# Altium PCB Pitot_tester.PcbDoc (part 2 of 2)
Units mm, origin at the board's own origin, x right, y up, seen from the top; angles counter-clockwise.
Board outline 94.03 x 112.06 mm, 2 copper layers (Top Layer, Bottom Layer), stack 1.658 mm thick; 71 components, 60 nets, 466 pads, 349 vias.
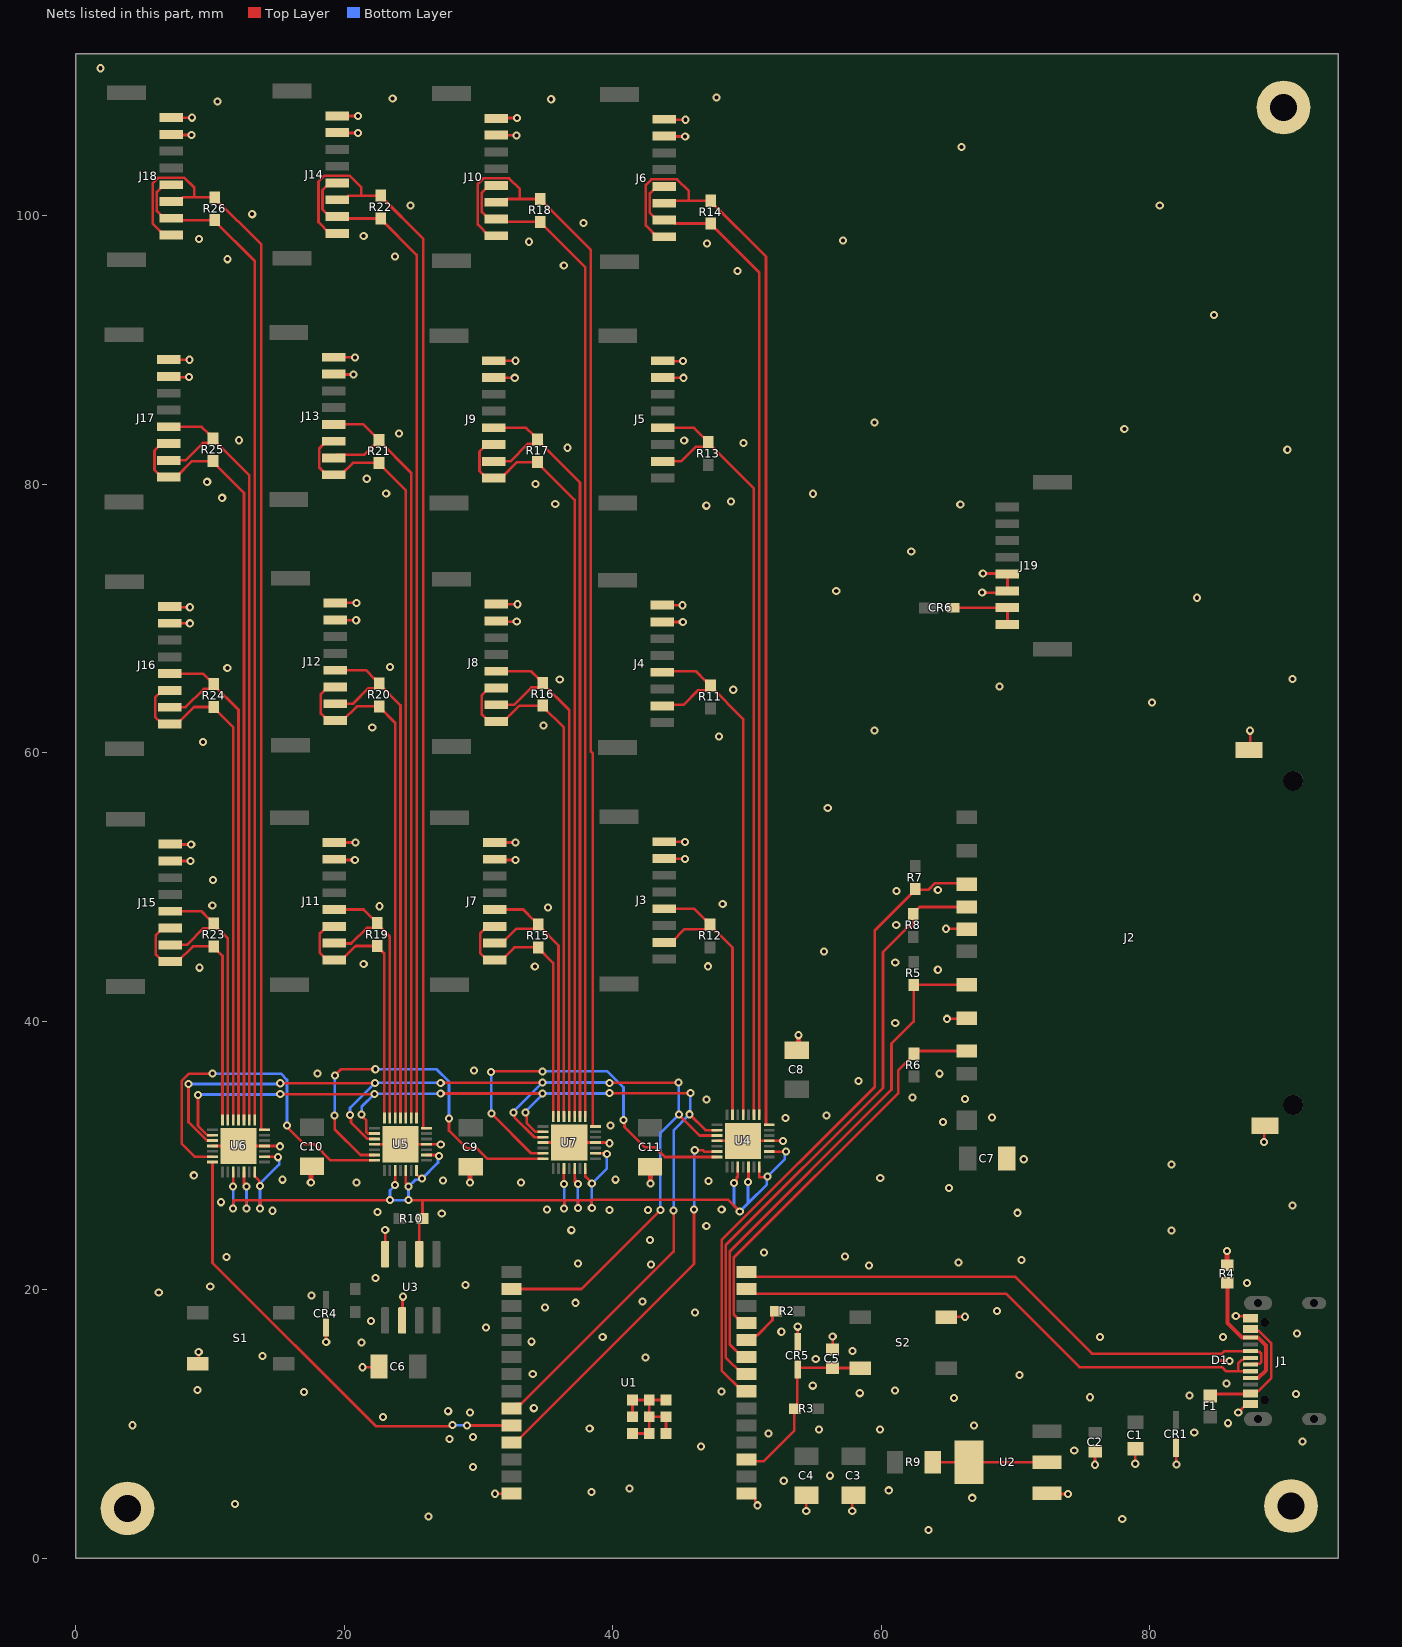
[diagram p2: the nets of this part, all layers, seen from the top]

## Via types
v1: diameter 0.61, hole 0.305, Top Layer to Bottom Layer, tented both sides, 187 vias
v2: diameter 0.6, hole 0.3, Top Layer to Bottom Layer, tented both sides, 162 vias

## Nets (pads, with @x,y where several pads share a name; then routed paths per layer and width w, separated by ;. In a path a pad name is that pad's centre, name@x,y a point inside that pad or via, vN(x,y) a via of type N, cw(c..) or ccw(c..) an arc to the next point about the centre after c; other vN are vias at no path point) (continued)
CANH_4: J6.1 J6.3 R14.2 U4.14 | length 83.5
  Top Layer w0.2: J6.1@43.836,98.444 43.29,98.444 42.459,99.274 42.459,102.307 42.877,102.724 44.795,102.724 45.658,101.861 45.658,101.129 ; J6.3@43.836,100.944 44.021,101.129 45.658,101.129 ; U4.14@51.651,32.29 51.411,32.29 51.41,32.291 51.41,96.964 47.295,101.079 R14.2@47.295,101.129 45.658,101.129
CANH_5: J7.1 J7.3 R15.2 U7.21 | length 20.7
  Top Layer w0.2: J7.3@31.187,47.071 30.64,47.071 30.11,46.541 30.11,45.101 30.64,44.571 J7.1@31.187,44.571 31.733,44.571 32.667,45.505 R15.2@34.442,45.505 34.442,45.455 35.554,44.344 U7.21@35.554,32.906
CANH_6: J8.1 J8.3 R16.2 U7.19 | length 39.2
  Top Layer w0.2: J8.3@31.318,64.825 30.772,64.825 30.242,64.294 30.242,62.855 30.772,62.325 J8.1@31.318,62.325 31.864,62.325 33.053,63.514 R16.2@34.773,63.514 34.773,63.464 36.354,61.882 U7.19@36.354,32.906
CANH_7: J9.1 J9.3 R17.2 U7.17 | length 57.7
  Top Layer w0.2: J9.3@31.14,82.96 30.594,82.96 30.064,82.43 30.064,80.99 30.594,80.46 J9.1@31.14,80.46 31.686,80.46 32.875,81.649 R17.2@34.392,81.649 34.392,81.599 37.154,78.837 U7.17@37.154,32.906
CANH_8: J10.1 J10.3 R18.2 U7.14 | length 84
  Top Layer w0.2: J10.3@30.772,101.014 J10.3@31.318,101.014 31.864,101.014 32.106,101.256 33.071,101.256 ; J10.1@31.318,98.514 30.772,98.514 29.942,99.344 29.942,102.377 30.359,102.794 32.277,102.794 33.071,102.001 33.071,101.256 ; U7.14@38.697,32.163 38.508,32.163 38.506,32.164 38.506,59.949 38.36,60.095 38.36,97.441 34.595,101.206 R18.2@34.595,101.256 33.071,101.256
CANH_9: J11.1 J11.3 R19.2 U5.21 | length 20.7
  Top Layer w0.2: J11.3@19.249,47.071 18.702,47.071 18.172,46.541 18.172,45.101 18.702,44.571 J11.1@19.249,44.571 19.795,44.571 20.83,45.607 R19.2@22.454,45.607 22.454,45.557 22.981,45.029 U5.21@22.981,32.779 U5.21@22.982,32.78
CANH_10: J12.1 J12.3 R20.2 U5.19 | length 38.9
  Top Layer w0.2: J12.3@19.325,64.902 18.779,64.902 18.248,64.371 18.248,62.932 18.779,62.402 J12.1@19.325,62.402 19.871,62.402 20.932,63.463 R20.2@22.606,63.463 22.606,63.413 23.781,62.238 U5.19@23.781,32.779
CANH_11: J13.1 J13.3 R21.2 U5.17 | length 57.4
  Top Layer w0.2: J13.3@19.202,83.214 18.656,83.214 18.126,82.684 18.126,81.244 18.656,80.714 J13.1@19.202,80.714 19.749,80.714 20.633,81.598 R21.2@22.581,81.598 22.581,81.548 24.581,79.548 U5.17@24.581,32.779
CANH_12: J14.1 J14.3 R22.2 U5.14 | length 83.5
  Top Layer w0.2: J14.1@19.452,98.698 18.906,98.698 18.075,99.528 18.075,102.561 18.493,102.978 20.411,102.978 21.26,102.129 21.26,101.51 ; J14.3@19.452,101.198 19.998,101.198 20.31,101.51 21.26,101.51 ; U5.14@26.124,32.036 25.884,32.036 25.883,32.037 25.883,98.285 22.708,101.46 R22.2@22.708,101.51 21.26,101.51
CANH_13: J15.1 J15.3 R23.2 U6.21 | length 20.9
  Top Layer w0.2: J15.3@7.031,46.944 6.485,46.944 5.955,46.414 5.955,44.974 6.485,44.444 J15.1@7.031,44.444 7.577,44.444 8.715,45.581 R23.2@10.262,45.581 10.262,45.531 10.916,44.877 U6.21@10.916,32.652
CANH_14: J16.1 J16.3 R24.2 U6.19 | length 39.2
  Top Layer w0.2: J16.3@6.98,64.648 6.434,64.648 5.904,64.117 5.904,62.678 6.434,62.148 J16.1@6.98,62.148 7.526,62.148 8.791,63.412 R24.2@10.262,63.412 10.262,63.362 11.716,61.908 U6.19@11.716,32.652 U6.19@11.717,32.653
CANH_15: J17.1 J17.3 R25.2 U6.17 | length 57.8
  Top Layer w0.2: J17.3@6.93,83.037 6.383,83.037 5.853,82.507 5.853,81.067 6.383,80.537 J17.1@6.93,80.537 7.476,80.537 8.664,81.725 R25.2@10.211,81.725 10.211,81.675 12.516,79.37 U6.17@12.516,32.652 U6.17@12.517,32.653
CANH_16: J18.1 J18.3 R26.2 U6.14 | length 83.6
  Top Layer w0.2: J18.1@7.107,98.571 6.561,98.571 5.731,99.401 5.731,102.434 6.148,102.851 8.066,102.851 8.814,102.104 8.814,101.383 ; J18.3@7.107,101.071 7.653,101.071 7.965,101.383 8.814,101.383 ; U6.14@14.059,31.909 13.819,31.909 13.818,31.91 13.818,97.853 10.338,101.333 R26.2@10.338,101.383 8.814,101.383
CANL: R10.1 U3.6 U4.3 U4.5 U4.7 U4.9 U5.3 U5.5 U5.7 U5.9 U6.3 U6.5 U6.7 U6.9 U7.3 U7.5 U7.7 U7.9 | length 94.7
  Top Layer w0.2: v2(11.709,26.06) 11.709,26.645 11.735,26.67 12.725,26.67 ; v2(11.709,27.686) 11.716,27.692 U6.3@11.716,28.765 ; v2@12.516,27.803 U6.5@12.516,28.765 ; v2(12.7,26.035) 12.7,26.645 12.725,26.67 ; U6.7@13.316,28.765 13.316,28.461 13.665,28.111 13.665,27.762 v2(13.716,27.711) ; v2(13.716,26.06) 13.716,26.645 13.741,26.67 ; U6.9@14.059,29.909 14.061,29.907 15.026,29.907 v2(15.062,29.87) ; v2(23.393,26.67) 13.741,26.67 ; v2(23.774,27.788) 23.781,27.794 U5.3@23.781,28.892 ; U5.5@24.581,28.892 24.581,27.93 24.79,27.721 v2(24.79,27.678) ; v2(24.774,26.67) 25.806,26.67 ; U5.7@25.381,28.892 25.381,28.588 25.698,28.27 v2(25.781,28.27) ; U3.6@25.578,22.993 25.578,25.058 R10.1@25.818,25.298 25.818,26.658 25.806,26.67 ; U5.9@26.124,30.036 26.126,30.034 26.989,30.034 v2(27.051,29.972) ; U7.3@36.354,29.019 36.354,27.883 v2(36.373,27.864) ; v2(36.373,26.035) 36.373,26.645 36.398,26.67 ; U7.5@37.154,29.019 37.154,28.313 37.186,28.281 v2@37.186,27.981 ; v2(37.414,26.086) 37.414,26.645 37.44,26.67 ; U7.7@37.954,29.019 37.954,28.43 38.329,28.055 38.329,28.016 v2(38.43,27.915) ; v2(38.43,26.086) 38.43,26.645 38.456,26.67 ; U7.9@38.697,30.163 38.699,30.161 39.486,30.161 v2(39.548,30.099) ; v2@49.225,28.083 49.225,28.357 49.308,28.44 U4.3@49.308,29.146 ; v2(49.454,25.832) 48.573,26.713 38.498,26.713 38.456,26.67 ; v2(50.063,28.016) 50.108,28.061 U4.5@50.108,29.146 ; U4.7@50.908,29.146 50.908,28.387 51.476,28.387 v2(51.537,28.448) ; U4.9@51.651,30.29 v2(52.889,30.29) ; 12.725,26.67 13.741,26.67 ; 25.806,26.67 36.398,26.67 ; 36.398,26.67 37.44,26.67 ; 37.44,26.67 38.456,26.67
  Bottom Layer w0.2: v2(11.709,26.06) v2(11.709,27.686) ; v2(12.7,26.035) 12.708,26.043 12.708,27.678 v2(12.716,27.686) ; v2(13.716,26.06) v2(13.716,27.711) 13.793,27.788 13.793,27.988 15.139,29.334 15.139,29.794 v2(15.062,29.87) ; v2(23.774,27.788) 23.393,27.407 v2(23.393,26.67) v2(24.774,26.67) 24.782,26.678 24.782,27.67 v2(24.79,27.678) 25.306,28.194 25.704,28.194 26.974,29.464 26.974,29.895 v2(27.051,29.972) ; v2(36.373,26.035) v2(36.373,27.864) ; v2(37.389,27.864) 37.389,26.111 v2(37.414,26.086) ; v2(38.43,26.086) v2(38.43,27.915) 39.548,29.032 v2(39.548,30.099) ; v2(49.022,27.965) 49.022,26.264 v2(49.454,25.832) 50.063,26.441 ; v2(50.063,28.016) 50.063,26.441 ; v2(52.889,30.29) 52.812,30.213 52.812,29.724 v2(51.537,28.448) 51.47,28.381 51.47,27.848 50.063,26.441
CANL_1: J3.2 J3.4 R12.1 U4.20 | length 22.8
  Top Layer w0.2: J3.2@43.815,45.878 44.361,45.878 45.346,46.863 46.944,46.863 47.244,47.163 R12.1@47.244,47.205 47.244,47.255 46.944,47.555 46.894,47.555 46.071,48.378 J3.4@43.815,48.378 ; R12.1@47.244,47.155 48.908,45.491 U4.20@48.908,33.033
CANL_2: J4.2 J4.4 R11.1 U4.18 | length 40.7
  Top Layer w0.2: J4.2@43.891,63.575 45.263,63.575 46.349,64.66 46.969,64.66 47.269,64.96 49.708,62.522 U4.18@49.708,33.033 ; J4.4@43.891,66.075 46.205,66.075 46.919,65.36 46.969,65.36 47.269,65.06 R11.1@47.269,65.01
CANL_3: J5.2 J5.4 R13.1 U4.16 | length 59.3
  Top Layer w0.2: J5.2@43.713,81.71 45.085,81.71 46.171,82.796 46.817,82.796 47.117,83.096 50.508,79.705 U4.16@50.508,33.033 ; J5.4@43.713,84.21 46.053,84.21 46.767,83.496 46.817,83.496 47.117,83.196 R13.1@47.117,83.146
CANL_4: J6.2 J6.4 R14.1 U4.15 | length 75.5
  Top Layer w0.2: J6.4@43.836,102.194 43.29,102.194 42.759,101.664 42.759,100.224 43.29,99.694 J6.2@43.836,99.694 44.382,99.694 44.647,99.429 R14.1@47.295,99.429 47.295,99.379 50.908,95.766 U4.15@50.908,33.033
CANL_5: J7.2 J7.4 R15.1 U7.20 | length 22.5
  Top Layer w0.2: J7.2@31.187,45.821 31.733,45.821 32.8,46.888 34.142,46.888 34.442,47.188 R15.1@34.442,47.205 34.442,47.255 34.142,47.555 34.092,47.555 33.327,48.321 J7.4@31.187,48.321 ; R15.1@34.442,47.155 35.954,45.644 U7.20@35.954,32.906
CANL_6: J8.2 J8.4 R16.1 U7.18 | length 41
  Top Layer w0.2: J8.2@31.318,63.575 32.639,63.575 33.928,64.864 34.473,64.864 34.773,65.164 36.754,63.182 U7.18@36.754,32.906 ; J8.4@31.318,66.075 33.912,66.075 34.423,65.564 34.473,65.564 34.773,65.264 R16.1@34.773,65.214
CANL_7: J9.2 J9.4 R17.1 U7.16 | length 59.2
  Top Layer w0.2: J9.2@31.14,81.71 32.36,81.71 33.649,82.999 34.092,82.999 34.392,83.299 37.554,80.137 U7.16@37.554,32.906 ; J9.4@31.14,84.21 33.531,84.21 34.042,83.699 34.092,83.699 34.392,83.399 R17.1@34.392,83.349
CANL_8: J10.2 J10.4 R18.1 U7.15 | length 75.4
  Top Layer w0.2: J10.4@31.318,102.264 30.772,102.264 30.242,101.734 30.242,100.294 30.772,99.764 J10.2@31.318,99.764 31.526,99.556 R18.1@34.595,99.556 34.595,99.506 37.954,96.147 U7.15@37.954,32.906
CANL_9: J11.2 J11.4 R19.1 U5.20 | length 22.4
  Top Layer w0.2: J11.2@19.249,45.821 19.277,45.793 20.507,45.793 21.671,46.957 22.154,46.957 R19.1@22.454,47.257 ; J11.4@19.249,48.321 21.439,48.321 22.104,47.657 22.154,47.657 22.454,47.357 R19.1@22.454,47.307 R19.1@22.454,47.257 ; U5.20@23.381,32.779 23.381,46.329 R19.1@22.454,47.257
CANL_10: J12.2 J12.4 R20.1 U5.18 | length 40.6
  Top Layer w0.2: J12.2@19.325,63.652 20.623,63.652 21.784,64.813 22.306,64.813 22.606,65.113 24.181,63.538 U5.18@24.181,32.779 ; J12.4@19.325,66.152 21.617,66.152 22.256,65.513 22.306,65.513 22.606,65.213 R20.1@22.606,65.163
CANL_11: J13.2 J13.4 R21.1 U5.16 | length 59.3
  Top Layer w0.2: J13.2@19.202,81.964 19.433,82.194 21.477,82.194 22.231,82.948 22.281,82.948 22.581,83.248 24.981,80.848 U5.16@24.981,32.779 ; J13.4@19.202,84.464 21.415,84.464 22.231,83.648 22.281,83.648 22.581,83.348 R21.1@22.581,83.298
CANL_12: J14.2 J14.4 R22.1 U5.15 | length 75.5
  Top Layer w0.2: J14.4@19.452,102.448 18.906,102.448 18.375,101.918 18.375,100.478 18.906,99.948 J14.2@19.452,99.948 19.59,99.81 R22.1@22.708,99.81 22.708,99.76 25.381,97.087 U5.15@25.381,32.779
CANL_13: J15.2 J15.4 R23.1 U6.20 | length 22.6
  Top Layer w0.2: J15.2@7.031,45.694 8.266,45.694 9.503,46.931 9.962,46.931 R23.1@10.262,47.231 ; J15.4@7.031,48.194 9.349,48.194 9.912,47.631 9.962,47.631 10.262,47.331 R23.1@10.262,47.281 R23.1@10.262,47.231 ; U6.20@11.316,32.652 11.316,46.177 R23.1@10.262,47.231
CANL_14: J16.2 J16.4 R24.1 U6.18 | length 40.8
  Top Layer w0.2: J16.2@6.98,63.398 8.177,63.398 9.541,64.762 9.962,64.762 10.262,65.062 12.116,63.208 U6.18@12.116,32.652 U6.18@12.117,32.653 ; J16.4@6.98,65.898 9.476,65.898 9.912,65.462 9.962,65.462 10.262,65.162 R24.1@10.262,65.112
CANL_15: J17.2 J17.4 R25.1 U6.16 | length 59.5
  Top Layer w0.2: J17.2@6.93,81.787 8.164,81.787 9.452,83.075 9.911,83.075 10.211,83.375 12.916,80.67 U6.16@12.916,32.652 U6.16@12.917,32.653 ; J17.4@6.93,84.287 9.349,84.287 9.861,83.775 9.911,83.775 10.211,83.475 R25.1@10.211,83.425
CANL_16: J18.2 J18.4 R26.1 U6.15 | length 75.6
  Top Layer w0.2: J18.4@7.107,102.321 6.561,102.321 6.031,101.791 6.031,100.351 6.561,99.821 J18.2@7.107,99.821 7.245,99.683 R26.1@10.338,99.683 10.338,99.633 13.316,96.655 U6.15@13.316,32.652
D+: D1.3 J1.A6 J1.B6 U1.14 | length 42.5
  Top Layer w0.2: U1.14@49.958,21.326 50.308,20.976 69.959,20.976 75.703,15.232 D1.3@85.367,15.232 85.561,15.426 J1.B6@87.5,15.426 87.55,15.376 88.18,15.376 88.297,15.258 88.297,14.593 88.18,14.476 87.55,14.476 J1.A6@87.5,14.426
D-: D1.2 J1.A7 J1.B7 U1.13 | length 41.8
  Top Layer w0.2: U1.13@49.958,20.056 50.308,19.706 69.296,19.706 74.77,14.232 D1.2@85.367,14.232 85.674,13.926 86.587,13.926 ; J1.B7@87.5,13.926 86.587,13.926 ; J1.A7@87.5,14.926 87.08,14.926 86.93,14.776 86.847,14.776 86.587,14.515 86.587,13.926
EN: C5.1 CR5.2 R3.1 S2.3 U1.3 | length 14
  Top Layer w0.2: U1.3@49.927,7.212 49.945,7.23 51.248,7.23 53.518,9.5 53.518,11.078 R3.1@53.582,11.142 53.734,11.294 53.734,14.027 CR5.2@53.772,14.065 53.772,14.146 53.81,14.184 C5.1@56.363,14.184 56.378,14.168 58.43,14.168 S2.3@58.446,14.153
GND: C1.1 C2.1 C3.1 C4.1 C5.2 C6.1 C7.1 C8.2 C9.2 C10.2 C11.2 CR1.1 CR4.1 CR5.1 D1.1 J1.A1_B12 J1.B1_A12 J2.3 J2.6 J2.12 J2.13 J3.7 J3.8 J4.7 J4.8 J5.7 J5.8 J6.7 J6.8 J7.7 J7.8 J8.7 J8.8 J9.7 J9.8 J10.7 J10.8 J11.7 J11.8 J12.7 J12.8 J13.7 J13.8 J14.7 J14.8 J15.7 J15.8 J16.7 J16.8 J17.7 J17.8 J18.7 J18.8 J19.5 J19.6 pad.5 R4.2 S1.2 S2.2 U1.1 U1.28 U1.29 U2.1 U3.2 U3.8 U4.11 U4.25 U4.29 U5.11 U5.25 U5.29 U6.11 U6.25 U6.29 U7.11 U7.25 U7.29 | length 119.1
  Top Layer w0.2: J17.7@6.93,88.037 6.981,87.986 v1(8.433,87.986) ; J17.8@6.93,89.287 6.936,89.281 v1(8.458,89.281) ; J16.8@6.98,70.898 7.037,70.841 v1(8.484,70.841) ; J16.7@6.98,69.648 v1(8.484,69.647) ; J15.8@7.031,53.194 7.063,53.162 v1(8.585,53.162) ; J15.7@7.031,51.944 v1(8.534,51.943) ; J18.7@7.107,106.071 7.159,106.02 v1(8.611,106.02) ; J18.8@7.107,107.321 7.114,107.315 v1(8.636,107.315) ; S1.2@9.068,14.483 9.144,14.559 v1(9.144,15.367) ; U6.25@10.173,30.709 U6.29@12.116,30.709 U6.11@14.059,30.709 14.061,30.707 15.191,30.707 v1(15.215,30.683) ; CR4.1@18.618,17.189 18.631,17.177 18.631,16.116 v1(18.644,16.104) ; J13.7@19.202,88.214 19.228,88.189 v1(20.676,88.189) ; J13.8@19.202,89.464 19.208,89.459 v1(20.803,89.459) ; J11.7@19.249,52.071 19.3,52.019 v1(20.777,52.019) ; J11.8@19.249,53.321 19.255,53.315 v1(20.828,53.315) ; J12.7@19.325,69.902 19.351,69.875 v1(20.879,69.875) ; J12.8@19.325,71.152 19.344,71.171 v1(20.904,71.171) ; J14.7@19.452,106.198 19.478,106.172 v1(21.006,106.172) ; J14.8@19.452,107.448 19.458,107.442 v1(21.006,107.442) ; v1(21.361,14.224) 22.528,14.224 C6.1@22.578,14.275 ; U5.25@22.238,30.836 U5.29@24.181,30.836 U5.11@26.124,30.836 26.126,30.834 27.154,30.834 v1(27.178,30.81) ; U3.8@23.038,22.993 v1(23.038,24.46) ; U3.2@24.308,18.053 24.333,18.079 24.333,19.456 v1(24.359,19.482) ; J9.7@31.14,87.96 31.166,87.935 v1(32.69,87.935) ; J9.8@31.14,89.21 31.146,89.205 v1(32.741,89.205) ; J7.7@31.187,52.071 31.238,52.019 v1(32.741,52.019) ; J7.8@31.187,53.321 31.193,53.315 v1(32.741,53.315) ; v1(31.217,4.801) 32.443,4.801 U1.28@32.458,4.816 ; J8.7@31.318,69.825 31.369,69.774 v1(32.842,69.774) ; J8.8@31.318,71.075 31.324,71.069 v1(32.893,71.069) ; J10.7@31.318,106.014 31.338,105.994 v1(32.817,105.994) ; J10.8@31.318,107.264 31.344,107.29 v1(32.868,107.29) ; U7.25@34.811,30.963 U7.29@36.754,30.963 U7.11@38.697,30.963 38.699,30.961 39.702,30.961 v1(39.751,30.912) ; U1.29@41.463,9.286 U1.29@42.713,9.286 U1.29@42.713,10.536 ; U1.29@41.463,10.536 U1.29@41.463,11.786 U1.29@42.713,11.786 ; J4.8@43.683,70.999 43.69,70.993 v1(45.187,70.993) ; J4.7@43.683,69.749 v1(45.212,69.748) ; J5.7@43.713,87.96 43.739,87.935 v1(45.263,87.935) ; J5.8@43.713,89.21 43.744,89.179 v1(45.237,89.179) ; J3.7@43.815,52.128 43.847,52.095 v1(45.364,52.095) ; J3.8@43.815,53.378 43.827,53.365 v1(45.364,53.365) ; J6.7@43.836,105.944 43.862,105.918 v1(45.39,105.918) ; J6.8@43.836,107.194 43.867,107.163 v1(45.415,107.163) ; U1.29@43.963,9.286 U1.29@43.963,10.536 U1.29@42.713,10.536 ; U1.29@43.963,11.786 U1.29@42.713,11.786 ; U4.25@47.765,31.09 U4.29@49.708,31.09 U4.11@51.651,31.09 v1(52.68,31.09) ; U1.1@49.958,4.816 50.258,4.816 50.608,4.466 50.608,4.215 50.775,4.048 v1(50.775,3.937) ; CR5.1@53.772,16.11 v1(53.772,17.247) ; v1(54.407,3.505) 54.407,4.667 C4.1@54.432,4.692 ; C5.2@56.363,15.534 56.378,15.549 v1(56.378,16.524) ; v1(57.836,3.505) 57.836,4.596 C3.1@57.932,4.692 ; v1(64.821,46.888) 66.344,46.888 J2.3@66.37,46.862 ; S2.2@64.846,17.953 64.876,17.983 v1(66.243,17.983) ; v1(64.897,40.183) 66.341,40.183 J2.6@66.37,40.212 ; v1(67.513,71.933) 69.266,71.933 J19.6@69.397,72.064 J19.5@69.397,73.314 69.357,73.355 v1(67.564,73.355) ; U2.1@72.332,4.842 72.398,4.775 v1(73.914,4.775) ; v1(75.921,6.96) 75.921,7.955 C2.1@75.932,7.967 ; v1(78.918,7.036) 78.918,8.128 C1.1@78.932,8.142 ; CR1.1@81.966,8.223 81.978,8.211 81.978,6.998 v1(81.991,6.985) ; D1.1@85.117,14.732 85.903,14.732 v2(85.954,14.681) ; v1(86.411,18.034) 87.336,18.034 J1.B1_A12@87.495,17.876 ; v1(86.589,10.846) v1(86.589,10.846) 87.22,11.476 J1.A1_B12@87.495,11.476 ; J2.13@87.38,60.212 87.478,60.309 v1(87.478,61.646) ; v1(88.519,31.013) 88.519,32.151 J2.12@88.58,32.212 ; U1.29@42.713,10.536 U1.29@42.713,11.786
  Top Layer w0.381: v1(17.501,27.991) 17.501,29.132 C10.2@17.577,29.208 ; v1(29.362,27.991) 29.362,29.106 C9.2@29.413,29.157 ; C11.2@42.774,29.157 42.799,29.132 v1(42.799,27.915) ; C8.2@53.696,37.848 53.823,37.975 v1(53.823,38.964) ; v1(85.75,22.885) 85.763,22.873 85.763,21.846 R4.2@85.776,21.834 R4.2@85.801,21.859
  other v1: 63.525,2.108 77.953,2.921 26.264,3.099 11.862,4.039 66.777,4.496 60.554,5.055 52.73,5.766 56.185,6.147 74.371,8.026 91.389,8.687 51.587,9.296 83.312,9.373 66.904,9.881 4.216,9.906 85.827,10.058 34.112,11.176 82.956,12.116 58.395,12.294 54.889,12.852 34.036,13.716 55.118,14.834 13.894,15.062 57.861,15.443 33.934,16.129 39.243,16.485 52.553,16.866 34.95,18.669 37.211,19.025 42.215,19.126 6.172,19.787 87.249,20.498 42.85,21.869 37.414,21.946 57.302,22.479 51.257,22.784 42.774,23.698 81.61,24.409 36.906,24.435 46.965,24.74 70.155,25.73 39.751,25.933 42.621,25.933 35.103,25.984 48.108,25.984 90.627,26.264 59.919,28.321 81.61,29.337 70.612,29.718 64.592,32.487 62.332,34.315 58.293,35.56 64.338,36.093 61.036,39.878 64.211,43.84 9.195,43.993 34.188,44.069 47.092,44.094 21.438,44.272 61.036,44.374 55.728,45.187 61.112,47.168 35.179,48.463 22.606,48.565 10.16,48.616 48.184,48.743 61.138,49.708 64.211,49.784 10.211,50.521 56.007,55.88 9.474,60.808 47.904,61.214 59.487,61.671 22.073,61.874 34.823,62.027 80.162,63.754 48.971,64.694 68.809,64.948 36.043,65.456 90.627,65.507 11.278,66.319 23.393,66.396 83.515,71.552 56.642,72.06 62.23,75.006 46.965,78.41 65.888,78.486 35.712,78.537 48.793,78.715 10.897,78.994 54.915,79.299 23.114,79.324 34.239,80.035 9.779,80.188 21.666,80.416 90.246,82.575 36.627,82.728 49.733,83.083 45.314,83.261 12.141,83.287 24.079,83.795 78.105,84.125 59.487,84.607 84.785,92.608 49.276,95.885 36.347,96.291 11.303,96.774 23.774,96.977 47.015,97.942 33.757,98.069 57.15,98.171 9.169,98.273 21.438,98.501 37.821,99.466 13.132,100.127 24.917,100.762 80.747,100.762 65.964,105.131 10.541,108.509 35.408,108.687 23.597,108.737 47.727,108.814 1.829,110.998
  other v2: 38.405,4.928 41.224,5.207 29.591,6.782 46.584,8.306 27.838,8.865 29.566,9.017 55.372,9.589 59.893,9.576 38.278,9.652 22.885,10.516 29.362,10.846 27.737,10.947 65.43,11.938 75.54,11.989 90.907,12.217 16.993,12.395 48.108,12.421 61.011,12.497 9.068,12.522 85.725,13.005 70.307,13.64 42.443,14.935 21.285,16.053 76.302,16.485 85.446,16.485 90.983,16.739 30.556,17.17 21.971,17.678 46.126,18.313 68.631,18.415 17.551,19.583 10.008,20.244 29.032,20.345 22.327,20.879 59.08,21.819 65.761,22.022 70.46,22.2 11.201,22.428 27.254,25.679 22.454,25.806 14.656,25.883 10.82,26.518 65.049,27.584 20.904,27.991 33.172,27.991 47.142,28.092 27.33,28.143 15.392,28.194 40.208,28.194 8.779,28.526 39.827,32.233 52.857,32.791 68.25,32.842 55.905,32.995 46.965,34.163 66.243,34.214 18.009,36.093 29.667,36.322
MAX_CS: U1.23 U4.23 U5.23 U6.23 U7.23 | length 80.5
  Top Layer w0.2: v2(9.093,34.519) 9.093,32.197 9.78,31.51 10.171,31.51 U6.23@10.173,31.509 ; v2(15.223,34.569) 22.225,34.569 v2(22.25,34.595) ; v2(21.285,33.045) 21.285,32.937 21.631,32.591 21.631,31.754 21.748,31.637 22.236,31.637 U5.23@22.238,31.636 ; v2(27.178,34.62) v2(34.773,34.62) ; U1.23@32.458,11.166 32.808,11.516 33.21,11.516 44.526,22.832 v2(44.526,25.908) ; v2(33.503,33.198) 33.579,33.121 33.579,32.41 34.225,31.764 34.809,31.764 U7.23@34.811,31.763 ; v2(39.751,34.646) v2(45.771,34.646) ; v2(45.72,33.071) 46.901,31.89 U4.23@47.765,31.89
  Bottom Layer w0.2: v2(9.093,34.519) 9.119,34.544 15.197,34.544 v2(15.223,34.569) ; v2(21.285,33.045) 21.285,33.63 v2(22.25,34.595) 27.127,34.595 27.153,34.62 v2(27.178,34.62) ; v2(33.503,33.198) 33.503,33.274 34.773,34.544 v2(34.773,34.62) 39.726,34.62 v2(39.751,34.646) ; v2(44.526,25.908) 44.526,31.877 v2(45.72,33.071) 45.771,33.122 v2(45.771,34.646)
MAX_MISO: U1.24 U6.28 | length 34.9
  Top Layer w0.2: U6.28@10.173,29.509 10.173,21.996 22.339,9.83 27.991,9.83 v2(28.067,9.906) ; v2(29.134,9.881) 32.443,9.881 U1.24@32.458,9.896
  Bottom Layer w0.2: v2(28.067,9.906) 28.08,9.893 29.121,9.893 v2(29.134,9.881)
MAX_MOSI: U1.25 U4.27 | length 29.3
  Top Layer w0.2: U1.25@32.458,8.626 32.758,8.626 46.05,21.918 v2(46.05,25.984) ; v2(46.101,30.39) 46.701,30.39 46.801,30.29 U4.27@47.765,30.29
  Bottom Layer w0.2: v2(46.05,25.984) 46.076,26.01 46.076,30.364 v2(46.101,30.39)
MAX_PAR: U5.27 U7.28 | length 28.4
  Top Layer w0.2: v2(19.279,32.969) 19.279,31.953 21.196,30.036 U5.27@22.238,30.036 ; v2(19.29,35.966) 19.747,36.424 v2(22.301,36.424) ; v2(27.788,32.741) 27.788,31.85 29.093,30.544 29.859,30.544 30.64,29.763 U7.28@34.811,29.763
  Bottom Layer w0.2: v2(19.279,32.969) 19.284,32.975 19.284,35.961 v2(19.29,35.966) ; v2(22.301,36.424) 26.869,36.424 27.788,35.505 v2(27.788,32.741)
MAX_SCK: U1.16 U4.24 U5.24 U6.24 U7.24 | length 81.2
  Top Layer w0.2: v2(8.382,35.331) 8.382,32.484 9.756,31.11 10.171,31.11 U6.24@10.173,31.109 ; v2(15.223,35.382) 22.25,35.382 v2(22.276,35.408) ; v2(20.422,33.02) 20.498,32.943 20.498,32.463 21.724,31.237 22.236,31.237 U5.24@22.238,31.236 ; v2(27.178,35.408) 34.747,35.408 v2(34.773,35.433) ; U1.16@32.458,20.056 37.658,20.056 v2(43.536,25.933) ; v2(32.614,33.198) 32.685,33.126 32.685,32.821 34.144,31.363 U7.24@34.811,31.363 ; v2(39.751,35.408) 44.882,35.408 v2(44.907,35.433) ; v2(44.931,33.069) 44.931,33.022 46.463,31.49 U4.24@47.765,31.49
  Bottom Layer w0.2: v2(8.382,35.331) 15.172,35.331 v2(15.223,35.382) ; v2(20.422,33.02) 20.422,33.553 v2(22.276,35.408) v2(27.178,35.408) ; v2(32.614,33.198) 32.614,33.274 v2(34.773,35.433) 39.726,35.433 v2(39.751,35.408) ; v2(43.536,25.933) 43.536,31.674 v2(44.931,33.069) 44.919,33.08 44.919,35.421 v2(44.907,35.433)
NetCR6_2: CR6.2 J19.7 J19.8 | length 5.3
  Top Layer w0.2: CR6.2@65.354,70.79 65.379,70.814 J19.7@69.397,70.814 J19.8@69.397,69.564
NetF1_2: F1.2 J1.A4_B9 J1.B4_A9 | length 9.7
  Top Layer w0.2: F1.2@84.541,12.086 F1.2@84.506,12.086 84.646,12.226 J1.A4_B9@87.445,12.226 ; J1.B4_A9@87.495,17.076 87.645,16.926 88.139,16.926 89.047,16.017 89.047,13.4 88.073,12.426 87.65,12.426 J1.A4_B9@87.5,12.276
NetJ1_A5: J1.A5 J1.B5 R4.1 | length 9.8
  Top Layer w0.3: R4.1@85.776,20.534 85.776,17.509 86.859,16.426 J1.B5@87.495,16.426 ; J1.A5@87.5,13.426 88.073,13.426 88.647,14 88.647,15.852 88.073,16.426 J1.B5@87.5,16.426
NetR2_2: R2.2 U1.10 | length 3.4
  Top Layer w0.2: U1.10@49.927,16.102 50.227,16.102 50.756,16.631 50.797,16.631 51.9,17.734 51.9,18.18 52.11,18.39 R2.2@52.16,18.39
NetR9_1: R9.1 U2.2 U2.4 | length 8.5
  Top Layer w0.2: R9.1@63.832,7.142 U2.4@66.532,7.142 U2.2@72.332,7.142
NetU4_28: U4.28 U7.27 | length 29.4
  Top Layer w0.2: v2(30.912,36.22) 30.963,36.271 v2(34.773,36.271) ; v2(30.963,33.122) 33.922,30.163 U7.27@34.811,30.163 ; v2(40.792,32.639) 40.869,32.562 40.869,32.129 42.39,30.608 43.156,30.608 43.874,29.89 U4.28@47.765,29.89
  Bottom Layer w0.2: v2(30.912,36.22) 30.937,36.195 30.937,33.147 v2(30.963,33.122) ; v2(34.773,36.271) 39.595,36.271 40.792,35.073 v2(40.792,32.639)
NetU5_28: U5.28 U6.27 | length 26.7
  Top Layer w0.2: U6.27@10.173,29.909 10.171,29.91 8.85,29.91 7.882,30.878 7.882,35.539 8.437,36.093 v2(10.185,36.093) ; v2(15.723,32.233) 15.723,32.129 17.008,30.844 17.774,30.844 18.982,29.636 U5.28@22.238,29.636
  Bottom Layer w0.2: v2(10.185,36.093) 15.261,36.093 15.723,35.632 v2(15.723,32.233)
SD_CLK: J2.5 R5.1 U1.9 | length 38.1
  Top Layer w0.2: U1.9@49.958,14.976 49.658,14.976 48.708,15.926 48.708,22.851 60.757,34.9 60.757,38.329 62.408,39.98 R5.1@62.408,42.711 R5.1@62.408,42.711 J2.5@66.37,42.712
SD_CS: J2.11 R8.1 U1.8 | length 45.2
  Top Layer w0.2: U1.8@49.958,13.706 49.658,13.706 48.408,14.956 48.408,23.313 60.122,35.027 60.122,45.165 61.991,47.034 62.174,47.034 62.382,47.242 R8.1@62.382,47.992 62.382,48.042 62.852,48.512 J2.11@66.37,48.512
SD_MISO: J2.7 R6.1 U1.11 | length 30.2
  Top Layer w0.2: U1.11@49.958,17.516 49.658,17.516 49.008,18.166 49.008,22.414 61.265,34.671 61.265,36.36 62.433,37.528 R6.1@62.433,37.578 62.433,37.628 62.587,37.782 J2.7@66.37,37.782
SD_MOSI: J2.2 R7.1 U1.7 | length 48.4
  Top Layer w0.2: U1.7@49.958,12.436 49.658,12.436 48.108,13.986 48.108,23.691 59.512,35.095 59.512,46.776 62.535,49.798 63.512,49.798 64.002,50.289 66.293,50.289 J2.2@66.37,50.212
pads on no net: J1. J1.A8 J1.B8 J1.SH1 J1.SH2 J1.SH3 J1.SH4 J2. J2.1 J2.8 J2.9 J3.9 J3.10 J4.9 J4.10 J5.9 J5.10 J6.9 J6.10 J7.9 J7.10 J8.9 J8.10 J9.9 J9.10 J10.9 J10.10 J11.9 J11.10 J12.9 J12.10 J13.9 J13.10 J14.9 J14.10 J15.9 J15.10 J16.9 J16.10 J17.9 J17.10 J18.9 J18.10 J19.1 J19.2 J19.3 J19.4 J19.9 J19.10 S1.1 S1.4 S2.1 S2.4 U1.4 U1.5 U1.6 U1.12 U1.17 U1.18 U1.21 U1.22 U1.26 U1.27 U3.5 U4.10 U4.12 U4.13 U5.10 U5.12 U5.13 U6.10 U6.12 U6.13 U7.10 U7.12 U7.13

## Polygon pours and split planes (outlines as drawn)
no net on Bottom Overlay "3V3" (solid): 30.764,88.591 19.764,88.591 19.764,79.591 30.764,79.591
GND on Top Layer "GND_L01_P007" (solid, remove dead copper, pour order 7): 0.508,111.633 0.635,111.506 93.345,111.506 93.345,0.508 0.508,0.508
GND on Bottom Layer "GND_L02_P008" (solid, remove dead copper, pour order 8): 0.508,0.508 0.508,111.481 0.533,111.506 93.345,111.506 93.345,0.508

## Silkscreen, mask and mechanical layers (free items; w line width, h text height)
Top Overlay:
  text "'.ThBoardName' '.ThVersion'" at 58.953,91.719 h1.27
  text "A" at 62.205,88.29 h15
  text "24V in" at 78.13,69.596 h1.52 r90
  text "EN" at 66.929,15.342 h1.52
  text "BOOT" at 9.83,11.354 h1.52
Bottom Overlay:
  pour cut-out: 22.589,86.711 cw(c22.686,86.711) 22.617,86.779 22.634,86.796 cw(c22.706,86.723) 22.706,86.826 22.969,86.826 cw(c22.969,86.698) 23.096,86.698 23.096,86.446 23.094,86.446 23.094,86.441 cw(c22.969,86.441) 22.969,86.316 22.694,86.316 cw(c22.694,86.426) 22.589,86.426
  pour cut-out: 22.589,87.461 cw(c22.714,87.461) 22.714,87.586 22.979,87.586 cw(c22.979,87.466) 23.099,87.466 23.099,87.211 cw(c22.969,87.211) 22.969,87.081 22.714,87.081 cw(c22.714,87.206) 22.589,87.206
  pour cut-out: 24.369,86.431 24.394,86.366 24.439,86.331 24.504,86.316 24.569,86.341 24.609,86.391 24.619,86.436 24.619,87.966 24.604,88.031 24.559,88.076 24.504,88.096 24.444,88.091 24.409,88.066 24.374,88.016 23.599,86.866 23.609,87.966 23.574,88.051 23.504,88.096 23.419,88.081 23.379,88.051 23.354,88.001 23.349,87.951 23.349,86.456 23.374,86.371 23.424,86.331 23.484,86.316 23.534,86.331 23.569,86.361 23.604,86.401 24.364,87.546
  pour cut-out: 26.114,86.521 26.139,86.466 26.134,86.396 26.094,86.346 26.039,86.321 25.959,86.331 25.929,86.356 24.899,87.381 24.874,87.441 24.879,87.501 24.904,87.541 24.954,87.581 24.999,87.591 25.044,87.581 25.079,87.561
  pour cut-out: 27.474,86.806 27.549,86.826 27.614,86.801 27.664,86.731 27.654,86.646 27.629,86.611 27.354,86.336 27.319,86.321 26.784,86.321 26.734,86.331 26.684,86.356 26.429,86.616 26.399,86.661 26.399,86.941 26.404,86.991 26.414,87.021 26.469,87.076 26.704,87.311 26.749,87.331 26.799,87.336 27.234,87.336 27.414,87.516 27.414,87.666 27.229,87.841 26.829,87.841 26.604,87.616 26.544,87.591 26.464,87.601 26.414,87.646 26.394,87.706 26.399,87.756 26.429,87.796 26.704,88.071 26.744,88.091 26.789,88.096 27.279,88.096 27.329,88.091 27.369,88.066 27.629,87.806 27.654,87.766 27.669,87.731 27.669,87.446 27.654,87.401 27.614,87.356 27.369,87.111 27.314,87.081 26.829,87.081 26.649,86.896 26.649,86.751 26.829,86.571 27.234,86.571
Board:
  the board outline again, w0.1

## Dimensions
0,0 to 94.031,0 on Fab Notes
0,0 to 0,112.065 on Fab Notes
